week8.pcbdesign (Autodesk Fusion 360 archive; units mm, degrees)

design "Plaquitapruebamartes"
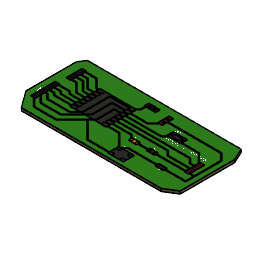
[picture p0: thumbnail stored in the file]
sketch "Boceto" plane through (0, 0, 0) normal (0, 0, 1) x axis (1, 0, 0)
  line L1 (61.595, 42.9047) -> (54.61, 52.4297)
  line L2 (141.3197, 42.9047) -> (61.595, 42.9047)
  line L3 (147.9872, 47.0322) -> (141.3197, 42.9047)
  line L4 (147.9872, 78.0728) -> (147.9872, 47.0322)
  line L5 (144.78, 85.09) -> (147.9872, 78.0728)
  line L6 (57.15, 85.09) -> (144.78, 85.09)
  line L7 (54.61, 81.28) -> (57.15, 85.09)
  line L8 (54.61, 52.4297) -> (54.61, 81.28)
canvas "Lienzo1"
canvas "Lienzo2"
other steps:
pcbextrude "PCBExtrude1"
extrude "Extruir" sketch "Boceto" blind 1.5 bodies "Placa"
pcbextrude "PCBExtrude1"
pcbextrude "PCBExtrude1"
pcbextrude "PCBExtrude1"
pcbextrude "PCBExtrude1"
box_primitive "CajaPrimitiva1" DistanceX 2.54 DistanceY 13.97 DistanceZ 0.1 OffsetDistanceX 0 OffsetDistanceY 0
box_primitive "CajaPrimitiva1" DistanceX 2.54 DistanceY 6.35 DistanceZ 0.1 OffsetDistanceX 0 OffsetDistanceY 0
box_primitive "CajaPrimitiva1" DistanceX 2.54 DistanceY 8.89 DistanceZ 0.1 OffsetDistanceX 0 OffsetDistanceY 0
box_primitive "CajaPrimitiva1" DistanceX 8 DistanceY 3.81 DistanceZ 0.1 OffsetDistanceX 0 OffsetDistanceY 0
box_primitive "CajaPrimitiva1" DistanceX 8.89 DistanceY 6.248 DistanceZ 0.1 OffsetDistanceX 0 OffsetDistanceY 0
box_primitive "CajaPrimitiva1" DistanceX 4.572 DistanceY 2.159 DistanceZ 0.1 OffsetDistanceX 0 OffsetDistanceY 0
box_primitive "CajaPrimitiva1" DistanceX 4.572 DistanceY 2.159 DistanceZ 0.1 OffsetDistanceX 0 OffsetDistanceY 0
box_primitive "CajaPrimitiva1" DistanceX 17.145 DistanceY 20.701 DistanceZ 0.1 OffsetDistanceX 0 OffsetDistanceY 0
pcbextrude "PCBExtrude2"
create_component "CrearComponentes1"
create_component "CrearComponentes2"
create_component "CrearComponentes3"
create_component "CrearComponentes4"
create_component "CrearComponentes5"
create_component "CrearComponentes6"
create_component "CrearComponentes1"
create_component "CrearComponentes2"
create_component "CrearComponentes3"
create_component "CrearComponentes4"
create_component "CrearComponentes5"
create_component "CrearComponentes6"
create_component "CrearComponentes7"
create_component "CrearComponentes8"
as_built_joint "Conforme a obra"
named bodies: "Placa"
